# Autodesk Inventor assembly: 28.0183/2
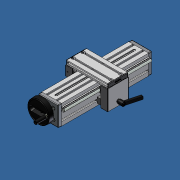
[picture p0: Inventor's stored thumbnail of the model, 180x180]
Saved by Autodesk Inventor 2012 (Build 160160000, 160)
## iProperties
Created: 2007-06
Part Number: 28.0183/2
Document SubType Name: Assembly
Designer: Andy Moles
Description: ADJUSTING UNIT VEW 90 WITH SIDE LOCK
Author: Andy Moles
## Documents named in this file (24)
- C:\Andys Backup Data\ANDY'S INVENTOR\INVENTOR LIBRARIES\PARTS LIBRARY\READY FOR USE MODULES LG\28.0183_2 ADJUSTING UNIT VEW 90 WITH SIDE LOCK.iam
- C:\Andys Backup Data\ANDY'S INVENTOR\INVENTOR LIBRARIES\PARTS LIBRARY\FASTENING ELEMENTS\NUTS\21.1351 M8 SQUARE NUT.ipt
- C:\Andys Backup Data\ANDY'S INVENTOR\INVENTOR LIBRARIES\PARTS LIBRARY\READY FOR USE MODULES LG\SUBCOMPONENTS\50.1264 BALL BEARING 10X30X9 6200 2RS DIN 625.ipt
- C:\Andys Backup Data\ANDY'S INVENTOR\INVENTOR LIBRARIES\PARTS LIBRARY\READY FOR USE MODULES LG\SUBCOMPONENTS\28.0204 HANDWHEEL 100mm.iam
- C:\Andys Backup Data\ANDY'S INVENTOR\INVENTOR LIBRARIES\PARTS LIBRARY\READY FOR USE MODULES LG\SUBCOMPONENTS\28.0205 BEARING PLATE 90X90 HANDWHEEL SIDE.ipt
- C:\Andys Backup Data\ANDY'S INVENTOR\INVENTOR LIBRARIES\PARTS LIBRARY\READY FOR USE MODULES LG\SUBCOMPONENTS\28.0206 BEARING PLATE 90X90 IDLER SIDE.ipt
- C:\Andys Backup Data\ANDY'S INVENTOR\INVENTOR LIBRARIES\PARTS LIBRARY\FASTENING ELEMENTS\SCREWS CAP\21.1204 M8X25.ipt
- C:\Andys Backup Data\ANDY'S INVENTOR\INVENTOR LIBRARIES\PARTS LIBRARY\READY FOR USE MODULES LG\SUBCOMPONENTS\28.0216 90x90 rail.iam
- C:\Andys Backup Data\ANDY'S INVENTOR\INVENTOR LIBRARIES\PARTS LIBRARY\READY FOR USE MODULES LG\SUBCOMPONENTS\28.0221 ACME SCREW 16X4.ipt
- C:\Andys Backup Data\ANDY'S INVENTOR\INVENTOR LIBRARIES\PARTS LIBRARY\FASTENING ELEMENTS\WASHERS\21.1326 DISC SPRING 20.ipt
- C:\Andys Backup Data\ANDY'S INVENTOR\INVENTOR LIBRARIES\PARTS LIBRARY\READY FOR USE MODULES LG\SUBCOMPONENTS\28.0225_1 LWG 32X45-90 90X19-NSC.ipt
- C:\Andys Backup Data\ANDY'S INVENTOR\INVENTOR LIBRARIES\PARTS LIBRARY\READY FOR USE MODULES LG\SUBCOMPONENTS\28.0126 SLIDE 45X32.ipt
- C:\Andys Backup Data\ANDY'S INVENTOR\INVENTOR LIBRARIES\PARTS LIBRARY\FASTENING ELEMENTS\SCREWS CAP\21.1200 M8X16.ipt
- C:\Andys Backup Data\ANDY'S INVENTOR\INVENTOR LIBRARIES\PARTS LIBRARY\END CAPS\22.1003_1 END CAP 45x32 Z Gray.iam
- C:\Andys Backup Data\ANDY'S INVENTOR\INVENTOR LIBRARIES\PARTS LIBRARY\READY FOR USE MODULES LG\SUBCOMPONENTS\28.9126 SIDE CLAMP 90X32.ipt
- C:\Andys Backup Data\ANDY'S INVENTOR\INVENTOR LIBRARIES\PARTS LIBRARY\COMPONENTS LG\21.1014_1 SLIDE LOCK WITH M6X65 STUD.ipt
- C:\Andys Backup Data\ANDY'S INVENTOR\INVENTOR LIBRARIES\PARTS LIBRARY\READY FOR USE MODULES LG\SUBCOMPONENTS\28.9127 SIDE LOCK SLIDE BAR 23.ipt
- C:\Andys Backup Data\ANDY'S INVENTOR\INVENTOR LIBRARIES\PARTS LIBRARY\COMPONENTS LG\22.1094 SLIDE RAIL LG.iam
- C:\Andys Backup Data\ANDY'S INVENTOR\INVENTOR LIBRARIES\PARTS LIBRARY\END CAPS\22.1061_1 END CAP 90X32 GRAY.ipt
- C:\Andys Backup Data\ANDY'S INVENTOR\INVENTOR LIBRARIES\PARTS LIBRARY\END CAPS\22.1014_1 END CAP 90X19 GRAY.ipt
- C:\Andys Backup Data\ANDY'S INVENTOR\INVENTOR LIBRARIES\PARTS LIBRARY\FASTENING ELEMENTS\NUTS\21.1330 M6 SQUARE NUT.ipt
- C:\Andys Backup Data\ANDY'S INVENTOR\INVENTOR LIBRARIES\PARTS LIBRARY\READY FOR USE MODULES LG\SUBCOMPONENTS\28.0255 Nut slide connector 20.ipt
- C:\Andys Backup Data\ANDY'S INVENTOR\INVENTOR LIBRARIES\PARTS LIBRARY\READY FOR USE MODULES LG\SUBCOMPONENTS\28.0257 BRONZE NUT 16X4 NOTCHED.ipt
- C:\Andys Backup Data\ANDY'S INVENTOR\INVENTOR LIBRARIES\PARTS LIBRARY\FASTENING ELEMENTS\SCREWS CAP\21.1235 M5X16.ipt
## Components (43 placed, 23 different names)
1. 28.0216 90x90 rail:1 [sub-assembly] — Mate:8, Flush:4, Mate:9, Mate:12, Angle:2, Angle:3, Mate:14, Flush:5, Flush:6, Flush:7, Flush:8, Angle:19, Angle:20, Mate:30
2. 50.1264 10X30X9 6200 2RS DIN 625 BALL BEARING:1 — Insert:15
3. 50.1264 10X30X9 6200 2RS DIN 625 BALL BEARING:2 — Insert:14, Insert:18
4. 28.0204 HANDWHEEL 100mm:1 [sub-assembly] — Insert:5, Angle:6, Angle:7
5. 28.0205 BEARING PLATE 90X90 HANDWHEEL SIDE:1 — Insert:5, Insert:6, Insert:7, Insert:8, Insert:9, Insert:15, Mate:12, Angle:2, Flush:7, Flush:8, Angle:7, Angle:21
6. 28.0206 BEARING PLATE 90X90 IDLER SIDE:1 — Insert:10, Insert:11, Insert:12, Insert:13, Insert:14, Angle:3, Mate:14, Flush:5, Flush:6
7. 21.1204  M8 x 25:1 — Insert:6
8. 21.1204  M8 x 25:2 — Insert:7
9. 21.1204  M8 x 25:3 — Insert:8
10. 21.1204  M8 x 25:4 — Insert:13
11. 21.1204  M8 x 25:5 — Insert:9
12. 21.1204  M8 x 25:6 — Insert:12
13. 21.1204  M8 x 25:7 — Insert:11
14. 21.1204  M8 x 25:8 — Insert:10
15. 28.0221 ACME SCREW 16X4:1 — Insert:16, Insert:17, Angle:6, Mate:29
16. 21.1326 DISC SPRING 20:1 — Insert:16
17. 21.1326 DISC SPRING 20:2 — Insert:17, Insert:18
18. 28.0225_1 LWG 32X45-90 90X19-NSC:1 — Mate:15, Flush:9, Insert:19, Insert:20, Insert:21, Insert:22, Insert:23, Insert:24, Angle:8, Angle:9, Insert:25, Insert:26, Angle:10, Angle:11, Flush:10, Mate:16, Flush:11, Flush:12, Flush:13, Mate:25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
19. 28.0126 SLIDE 45X32:1 — Mate:15, Flush:9, Flush:10, Insert:28, Angle:12, Insert:29, Angle:15, Mate:19, Mate:20
20. 21.1200 M8 x 16:1 — Insert:20
21. 21.1200 M8 x 16:2 — Insert:19
22. 21.1200 M8 x 16:3 — Insert:21
23. 21.1200 M8 x 16:4 — Insert:22
24. 21.1351 M8 SQUARE NUT:2 — Insert:23, Angle:9
25. 21.1351 M8 SQUARE NUT:3 — Insert:24, Angle:8
26. 21.1351 M8 SQUARE NUT:4 — Insert:25, Angle:10
27. 21.1351 M8 SQUARE NUT:5 — Insert:26, Angle:11
28. 22.1003\1 END CAP 45x32 Z Gray:1 [sub-assembly] — Insert:28, Angle:12
29. 22.1003\1 END CAP 45x32 Z Gray:2 [sub-assembly] — Insert:29, Angle:15
30. 28.9126 SIDE CLAMP 90X32:1 — Mate:16, Flush:11, Flush:12, Insert:30, Mate:17, Angle:16, Mate:21, Flush:14, Mate:22, Mate:23, Flush:15, Flush:16, Mate:24, Flush:17, Flush:18
31. 21.1014_1 SLIDE LOCK WITH M6X65 STUD:1 — Insert:30, Mate:18, Mate:27
32. 28.9127 SIDE LOCK SLIDE BAR 23:1 — Mate:17, Mate:18, Angle:16, Mate:28, Angle:17
33. 22.1094 SLIDE RAIL LG:1 [sub-assembly] — Mate:21, Flush:14, Mate:22
34. 22.1094 SLIDE RAIL LG:2 [sub-assembly] — Mate:19, Flush:13, Mate:20, Mate:30
35. 22.1061_1 END CAP 90X32 GRAY:1 — Mate:23, Flush:15, Flush:16
36. 22.1061_1 END CAP 90X32 GRAY:2 — Mate:24, Flush:17, Flush:18
37. 22.1014_1 END CAP 90X19 GRAY:1 — Mate:25, Flush:19, Flush:20
38. 22.1014_1 END CAP 90X19 GRAY:2 — Mate:26, Flush:21, Flush:22
39. 21.1330 M6 SQUARE NUT:1 — Mate:27, Mate:28, Angle:17
40. 28.0255 Nut slide connector 20:1 — Insert:31, Angle:18, Mate:31
41. 28.0257 BRONZE NUT 16X4 NOTCHED:1 — Mate:29, Angle:19, Mate:31
42. 21.1235  M5 x 16:1 — Insert:32
43. 21.1235  M5 x 16:2 — Insert:33
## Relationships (84: Insert 28, Mate 21, Flush 19, Angle 16)
- Insert:5: 28.0204 HANDWHEEL 100mm:1 ↔ 28.0205 BEARING PLATE 90X90 HANDWHEEL SIDE:1
- Insert:6: 28.0205 BEARING PLATE 90X90 HANDWHEEL SIDE:1 ↔ 21.1204  M8 x 25:1
- Insert:7: 28.0205 BEARING PLATE 90X90 HANDWHEEL SIDE:1 ↔ 21.1204  M8 x 25:2
- Insert:8: 28.0205 BEARING PLATE 90X90 HANDWHEEL SIDE:1 ↔ 21.1204  M8 x 25:3
- Insert:9: 28.0205 BEARING PLATE 90X90 HANDWHEEL SIDE:1 ↔ 21.1204  M8 x 25:5
- Insert:10: 28.0206 BEARING PLATE 90X90 IDLER SIDE:1 ↔ 21.1204  M8 x 25:8
- Insert:11: 28.0206 BEARING PLATE 90X90 IDLER SIDE:1 ↔ 21.1204  M8 x 25:7
- Insert:12: 28.0206 BEARING PLATE 90X90 IDLER SIDE:1 ↔ 21.1204  M8 x 25:6
- Insert:13: 28.0206 BEARING PLATE 90X90 IDLER SIDE:1 ↔ 21.1204  M8 x 25:4
- Mate:8: 28.0216 90x90 rail:1
- Flush:4: 28.0216 90x90 rail:1
- Mate:9: 28.0216 90x90 rail:1
- Insert:14: 50.1264 10X30X9 6200 2RS DIN 625 BALL BEARING:2 ↔ 28.0206 BEARING PLATE 90X90 IDLER SIDE:1
- Insert:15: 50.1264 10X30X9 6200 2RS DIN 625 BALL BEARING:1 ↔ 28.0205 BEARING PLATE 90X90 HANDWHEEL SIDE:1
- Mate:12: 28.0216 90x90 rail:1 ↔ 28.0205 BEARING PLATE 90X90 HANDWHEEL SIDE:1
- Angle:2: 28.0216 90x90 rail:1 ↔ 28.0205 BEARING PLATE 90X90 HANDWHEEL SIDE:1
- Angle:3: 28.0216 90x90 rail:1 ↔ 28.0206 BEARING PLATE 90X90 IDLER SIDE:1
- Mate:14: 28.0216 90x90 rail:1 ↔ 28.0206 BEARING PLATE 90X90 IDLER SIDE:1
- Flush:5: 28.0216 90x90 rail:1 ↔ 28.0206 BEARING PLATE 90X90 IDLER SIDE:1
- Flush:6: 28.0216 90x90 rail:1 ↔ 28.0206 BEARING PLATE 90X90 IDLER SIDE:1
- Flush:7: 28.0216 90x90 rail:1 ↔ 28.0205 BEARING PLATE 90X90 HANDWHEEL SIDE:1
- Flush:8: 28.0216 90x90 rail:1 ↔ 28.0205 BEARING PLATE 90X90 HANDWHEEL SIDE:1
- Insert:16: 28.0221 ACME SCREW 16X4:1 ↔ 21.1326 DISC SPRING 20:1
- Insert:17: 28.0221 ACME SCREW 16X4:1 ↔ 21.1326 DISC SPRING 20:2
- Insert:18: 50.1264 10X30X9 6200 2RS DIN 625 BALL BEARING:2 ↔ 21.1326 DISC SPRING 20:2
- Angle:6: 28.0204 HANDWHEEL 100mm:1 ↔ 28.0221 ACME SCREW 16X4:1
- Angle:7: 28.0204 HANDWHEEL 100mm:1 ↔ 28.0205 BEARING PLATE 90X90 HANDWHEEL SIDE:1
- Mate:15: 28.0225_1 LWG 32X45-90 90X19-NSC:1 ↔ 28.0126 SLIDE 45X32:1
- Flush:9: 28.0225_1 LWG 32X45-90 90X19-NSC:1 ↔ 28.0126 SLIDE 45X32:1
- Insert:19: 28.0225_1 LWG 32X45-90 90X19-NSC:1 ↔ 21.1200 M8 x 16:2
- Insert:20: 28.0225_1 LWG 32X45-90 90X19-NSC:1 ↔ 21.1200 M8 x 16:1
- Insert:21: 28.0225_1 LWG 32X45-90 90X19-NSC:1 ↔ 21.1200 M8 x 16:3
- Insert:22: 28.0225_1 LWG 32X45-90 90X19-NSC:1 ↔ 21.1200 M8 x 16:4
- Insert:23: 28.0225_1 LWG 32X45-90 90X19-NSC:1 ↔ 21.1351 M8 SQUARE NUT:2
- Insert:24: 28.0225_1 LWG 32X45-90 90X19-NSC:1 ↔ 21.1351 M8 SQUARE NUT:3
- Angle:8: 28.0225_1 LWG 32X45-90 90X19-NSC:1 ↔ 21.1351 M8 SQUARE NUT:3
- Angle:9: 28.0225_1 LWG 32X45-90 90X19-NSC:1 ↔ 21.1351 M8 SQUARE NUT:2
- Insert:25: 28.0225_1 LWG 32X45-90 90X19-NSC:1 ↔ 21.1351 M8 SQUARE NUT:4
- Insert:26: 28.0225_1 LWG 32X45-90 90X19-NSC:1 ↔ 21.1351 M8 SQUARE NUT:5
- Angle:10: 28.0225_1 LWG 32X45-90 90X19-NSC:1 ↔ 21.1351 M8 SQUARE NUT:4
- Angle:11: 28.0225_1 LWG 32X45-90 90X19-NSC:1 ↔ 21.1351 M8 SQUARE NUT:5
- Flush:10: 28.0225_1 LWG 32X45-90 90X19-NSC:1 ↔ 28.0126 SLIDE 45X32:1
- Insert:28: 28.0126 SLIDE 45X32:1 ↔ 22.1003\1 END CAP 45x32 Z Gray:1
- Angle:12: 28.0126 SLIDE 45X32:1 ↔ 22.1003\1 END CAP 45x32 Z Gray:1
- Insert:29: 28.0126 SLIDE 45X32:1 ↔ 22.1003\1 END CAP 45x32 Z Gray:2
- Angle:15: 28.0126 SLIDE 45X32:1 ↔ 22.1003\1 END CAP 45x32 Z Gray:2
- Mate:16: 28.0225_1 LWG 32X45-90 90X19-NSC:1 ↔ 28.9126 SIDE CLAMP 90X32:1
- Flush:11: 28.0225_1 LWG 32X45-90 90X19-NSC:1 ↔ 28.9126 SIDE CLAMP 90X32:1
- Flush:12: 28.0225_1 LWG 32X45-90 90X19-NSC:1 ↔ 28.9126 SIDE CLAMP 90X32:1
- Insert:30: 28.9126 SIDE CLAMP 90X32:1 ↔ 21.1014_1 SLIDE LOCK WITH M6X65 STUD:1
- Mate:17: 28.9126 SIDE CLAMP 90X32:1 ↔ 28.9127 SIDE LOCK SLIDE BAR 23:1
- Mate:18: 21.1014_1 SLIDE LOCK WITH M6X65 STUD:1 ↔ 28.9127 SIDE LOCK SLIDE BAR 23:1
- Angle:16: 28.9126 SIDE CLAMP 90X32:1 ↔ 28.9127 SIDE LOCK SLIDE BAR 23:1
- Mate:19: 28.0126 SLIDE 45X32:1 ↔ 22.1094 SLIDE RAIL LG:2
- Flush:13: 28.0225_1 LWG 32X45-90 90X19-NSC:1 ↔ 22.1094 SLIDE RAIL LG:2
- Mate:20: 28.0126 SLIDE 45X32:1 ↔ 22.1094 SLIDE RAIL LG:2
- Mate:21: 28.9126 SIDE CLAMP 90X32:1 ↔ 22.1094 SLIDE RAIL LG:1
- Flush:14: 28.9126 SIDE CLAMP 90X32:1 ↔ 22.1094 SLIDE RAIL LG:1
- Mate:22: 28.9126 SIDE CLAMP 90X32:1 ↔ 22.1094 SLIDE RAIL LG:1
- Mate:23: 28.9126 SIDE CLAMP 90X32:1 ↔ 22.1061_1 END CAP 90X32 GRAY:1
- Flush:15: 28.9126 SIDE CLAMP 90X32:1 ↔ 22.1061_1 END CAP 90X32 GRAY:1
- Flush:16: 28.9126 SIDE CLAMP 90X32:1 ↔ 22.1061_1 END CAP 90X32 GRAY:1
- Mate:24: 28.9126 SIDE CLAMP 90X32:1 ↔ 22.1061_1 END CAP 90X32 GRAY:2
- Flush:17: 28.9126 SIDE CLAMP 90X32:1 ↔ 22.1061_1 END CAP 90X32 GRAY:2
- Flush:18: 28.9126 SIDE CLAMP 90X32:1 ↔ 22.1061_1 END CAP 90X32 GRAY:2
- Mate:25: 28.0225_1 LWG 32X45-90 90X19-NSC:1 ↔ 22.1014_1 END CAP 90X19 GRAY:1
- Flush:19: 28.0225_1 LWG 32X45-90 90X19-NSC:1 ↔ 22.1014_1 END CAP 90X19 GRAY:1
- Flush:20: 28.0225_1 LWG 32X45-90 90X19-NSC:1 ↔ 22.1014_1 END CAP 90X19 GRAY:1
- Mate:26: 28.0225_1 LWG 32X45-90 90X19-NSC:1 ↔ 22.1014_1 END CAP 90X19 GRAY:2
- Flush:21: 28.0225_1 LWG 32X45-90 90X19-NSC:1 ↔ 22.1014_1 END CAP 90X19 GRAY:2
- Flush:22: 28.0225_1 LWG 32X45-90 90X19-NSC:1 ↔ 22.1014_1 END CAP 90X19 GRAY:2
- Mate:27: 21.1014_1 SLIDE LOCK WITH M6X65 STUD:1 ↔ 21.1330 M6 SQUARE NUT:1
- Mate:28: 28.9127 SIDE LOCK SLIDE BAR 23:1 ↔ 21.1330 M6 SQUARE NUT:1
- Angle:17: 28.9127 SIDE LOCK SLIDE BAR 23:1 ↔ 21.1330 M6 SQUARE NUT:1
- Insert:31: 28.0225_1 LWG 32X45-90 90X19-NSC:1 ↔ 28.0255 Nut slide connector 20:1
- Angle:18: 28.0225_1 LWG 32X45-90 90X19-NSC:1 ↔ 28.0255 Nut slide connector 20:1
- Mate:29: 28.0221 ACME SCREW 16X4:1 ↔ 28.0257 BRONZE NUT 16X4 NOTCHED:1
- Angle:19: 28.0216 90x90 rail:1 ↔ 28.0257 BRONZE NUT 16X4 NOTCHED:1
- Angle:20: 28.0216 90x90 rail:1 ↔ 28.0225_1 LWG 32X45-90 90X19-NSC:1
- Angle:21: 28.0205 BEARING PLATE 90X90 HANDWHEEL SIDE:1 ↔ 28.0225_1 LWG 32X45-90 90X19-NSC:1
- Mate:30: 28.0216 90x90 rail:1 ↔ 22.1094 SLIDE RAIL LG:2
- Mate:31: 28.0255 Nut slide connector 20:1 ↔ 28.0257 BRONZE NUT 16X4 NOTCHED:1
- Insert:32: 28.0225_1 LWG 32X45-90 90X19-NSC:1 ↔ 21.1235  M5 x 16:1
- Insert:33: 28.0225_1 LWG 32X45-90 90X19-NSC:1 ↔ 21.1235  M5 x 16:2
